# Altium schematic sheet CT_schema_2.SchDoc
size 200 x 173 mm
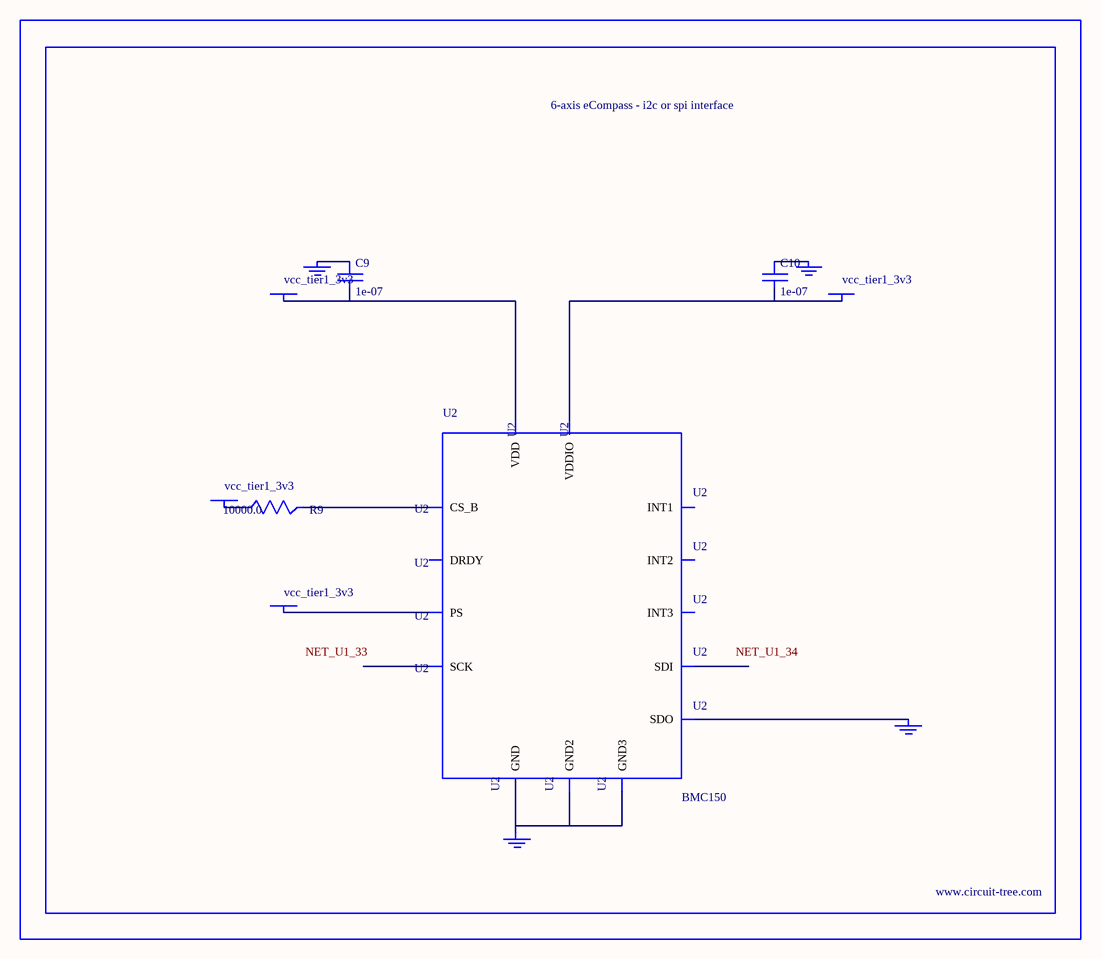
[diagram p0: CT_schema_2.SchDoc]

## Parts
BORDER1  (no value)
C9  1e-07  [C0402]
C10  1e-07  [C0402]
GND_INSTANCE_1_0  (no value)
GND_INSTANCE_1_1  (no value)
GND_INSTANCE_1_2  (no value)
GND_INSTANCE_1_3  (no value)
POWER_INSTANCE_1_0  vcc_tier1_3v3
POWER_INSTANCE_1_1  vcc_tier1_3v3
POWER_INSTANCE_1_2  vcc_tier1_3v3
POWER_INSTANCE_1_3  vcc_tier1_3v3
R9  10000.0  [R0603]
U2  BMC150  [LGA14R35P5X6_200X200X100]

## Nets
NetC9_1: C9.1 GND_INSTANCE_1_1.0(GND)
NetC9_2: C9.2 POWER_INSTANCE_1_0.0(PWR) U2.8(VDD)
NetC10_1: C10.1 GND_INSTANCE_1_2.0(GND)
NetC10_2: C10.2 POWER_INSTANCE_1_1.0(PWR) U2.10(VDDIO)
NetGND_INSTANCE_1_0_0: GND_INSTANCE_1_0.0(GND) U2.1(SDO)
NetGND_INSTANCE_1_3_0: GND_INSTANCE_1_3.0(GND) U2.6(GND) U2.7(GND2) U2.9(GND3)
NetPOWER_INSTANCE_1_2_0: POWER_INSTANCE_1_2.0(PWR) R9.1
NetPOWER_INSTANCE_1_3_0: POWER_INSTANCE_1_3.0(PWR) U2.13(PS)
NetR9_2: R9.2 U2.12(CS_B)

Not connected (* = marked no-connect by the designer): U2 2(INT1) 3(INT2) 4(DRDY) 5(INT3) 11(SCK) 14(SDI)

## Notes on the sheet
- Labels drawn without touching a wire or pin: NET_U1_33, NET_U1_34

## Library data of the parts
BORDER1 = BORDER_PAGE1
C9 C10 = C0402C104K3RACTU
GND_INSTANCE_1_0-GND_INSTANCE_1_3 = GND
POWER_INSTANCE_1_0-POWER_INSTANCE_1_3 = PWR
R9 = RC0603JR-0710KL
